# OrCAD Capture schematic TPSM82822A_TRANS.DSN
size E; title: TPSM82822A 2-A High Efficiency Step-Down  Converter; rev: 1.0; note: Datasheet: SLVSEP0F                EVM:SLVUBR5D; note: Synchronous Step Down Converter; note: MicroSiP™ Power Module with Integrated Inductor
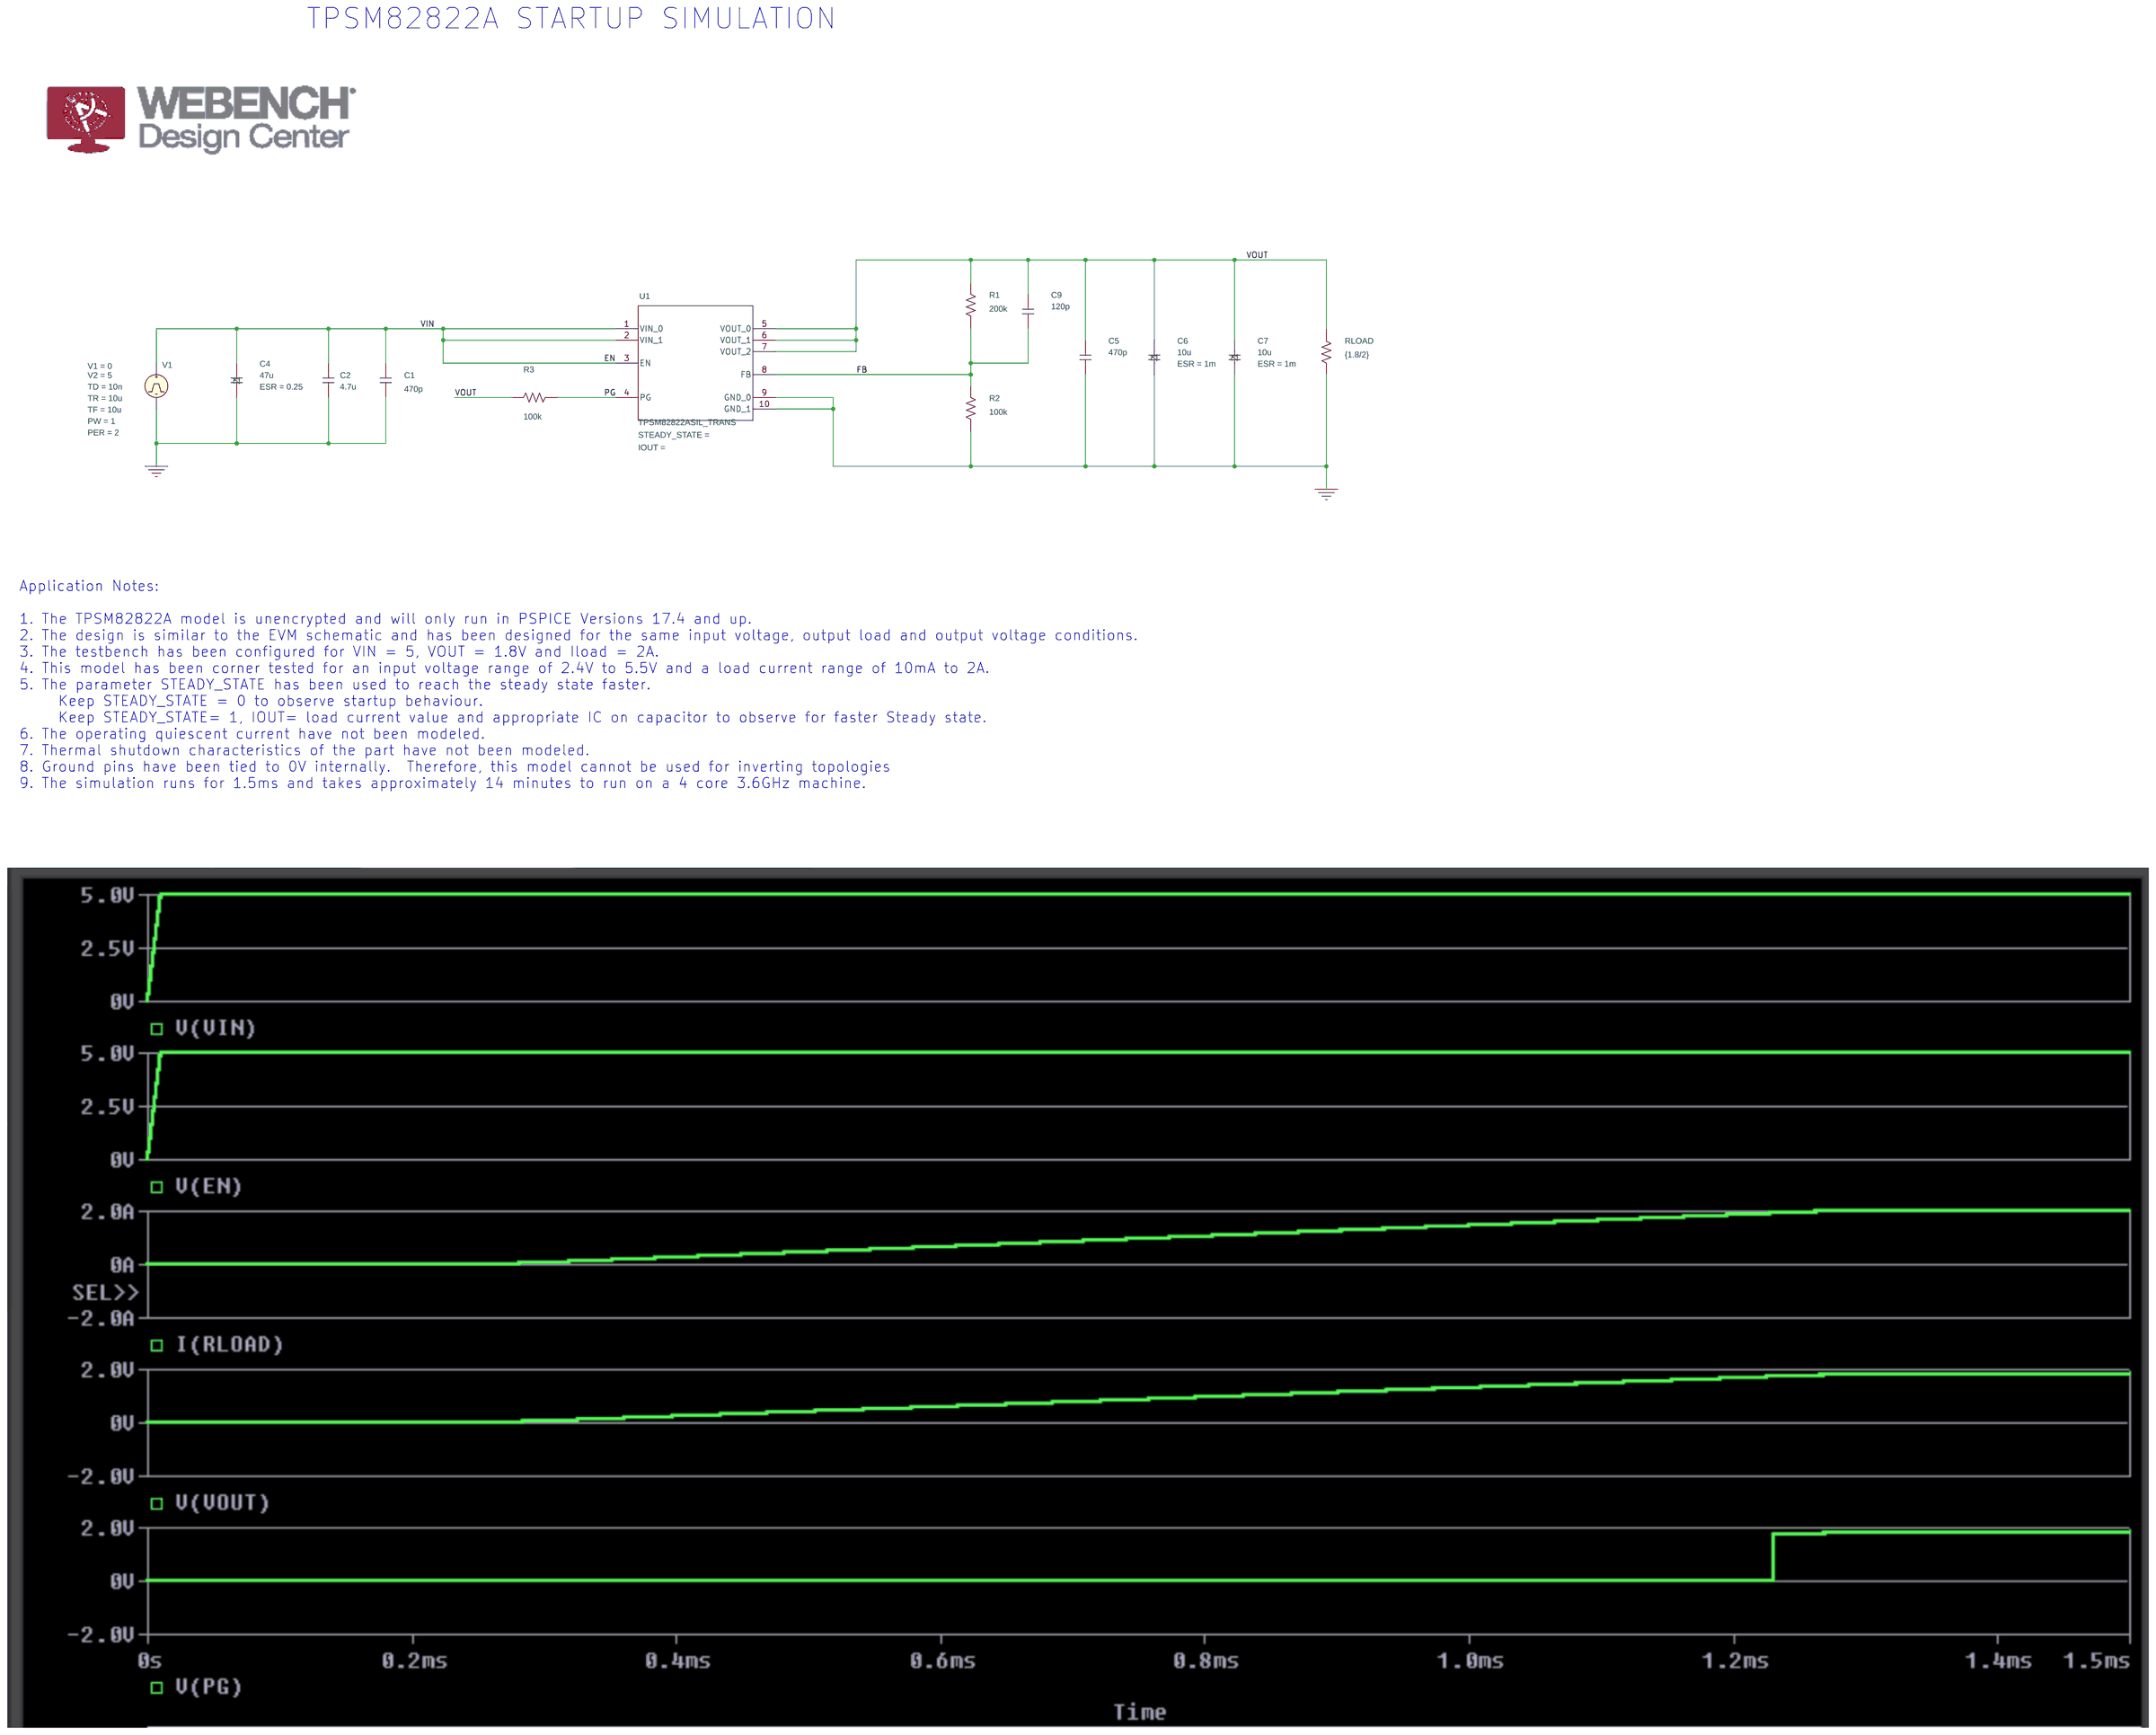
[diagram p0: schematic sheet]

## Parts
C1  470p  [RAD/CK05]
C2  4.7u  [RAD/CK05]
C4  CESR
C5  470p  [RAD/CK05]
C6  CESR
C7  CESR
C9  120p  [RAD/CK05]
R1  200k  [AX/RC05]
R2  100k  [AX/RC05]
R3  100k  [AX/RC05]
RLOAD  {1.8/2}  [AX/RC05]
U1  TPSM82822ASIL_TRANS  [SIL0010D-MFG]
V1  VPULSE

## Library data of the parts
C1 C2 = C: IC: 0
C4 = CESR: C: 47u; ESR: 0.25; PSpiceTemplate: X^@REFDES %1 %2 @MODEL PARAMS: ?C|C=@C||C=10U| ?ESR|ESR=@ESR||ESR=2M| ?IC|IC=@IC||IC=1N| ?; X: 1
C5 C9 = C
C6 = CESR_2: C: 10u; ESR: 1m; IC: 0; PSpiceTemplate: X^@REFDES %1 %2 @MODEL PARAMS: ?C|C=@C||C=10U| ?ESR|ESR=@ESR||ESR=2M| ?IC|IC=@IC||IC=1N| ?; X: 1
C7 = CESR_1: C: 10u; ESR: 1m; IC: 0; PSpiceTemplate: X^@REFDES %1 %2 @MODEL PARAMS: ?C|C=@C||C=10U| ?ESR|ESR=@ESR||ESR=2M| ?IC|IC=@IC||IC=1N| ?; X: 1
R1-R3 RLOAD = R
U1 = TPSM82822ASIL_TRANS
V1 = VPULSE: PER: 2; PW: 1; TD: 10n; TF: 10u; TR: 10u; V1: 0; V2: 5

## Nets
0: C1.2 C2.2 C4.2 C5.2 C6.2 C7.2 R2.1 RLOAD.2 U1.9(GND_0) U1.10(GND_1) V1.2(-)
EN: C1.1 C2.1 C4.1 U1.1(VIN_0) U1.2(VIN_1) U1.3(EN) V1.1(+)
FB: C9.2 R1.1 R2.2 U1.8(FB)
PG: R3.1 U1.4(PG)
VOUT: C5.1 C6.1 C7.1 C9.1 R1.2 R3.2 RLOAD.1 U1.5(VOUT_0) U1.6(VOUT_1) U1.7(VOUT_2)

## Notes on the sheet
- TPSM82822A STARTUP SIMULATION
- Application Notes:
  1. The TPSM82822A model is unencrypted and will only run in PSPICE Versions 17.4 and up.
  2. The design is similar to the EVM schematic and has been designed for the same input voltage, output load and output voltage conditions.
  3. The testbench has been configured for VIN = 5, VOUT = 1.8V and Iload = 2A.
  4. This model has been corner tested for an input voltage range of 2.4V to 5.5V and a load current range of 10mA to 2A.
  5. The parameter STEADY_STATE has been used to reach the steady state faster.
       Keep STEADY_STATE = 0 to observe startup behaviour.
       Keep STEADY_STATE= 1, IOUT= load current value and appropriate IC on capacitor to observe for faster Steady state.
  6. The operating quiescent current have not been modeled.
  7. Thermal shutdown characteristics of the part have not been modeled.
  8. Ground pins have been tied to 0V internally.  Therefore, this model cannot be used for inverting topologies
  9. The simulation runs for 1.5ms and takes approximately 14 minutes to run on a 4 core 3.6GHz machine.
